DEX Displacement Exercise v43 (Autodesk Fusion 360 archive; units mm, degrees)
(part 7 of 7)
sketch "Sketch40" plane through (0, 0, 0) normal (0, 1, 0) x axis (1, 0, 0)
  line L1 (-93.35, 0) -> (5.1, 0)
  line L2 (-93.35, 50) -> (-93.35, 0)
  line L3 (5.1, 50) -> (-93.35, 50)
  line L4 (5.1, 0) -> (5.1, 50)
  line L5 (-12.25, 50) -> (12.25, 50)
  line L6 (-12.25, 0) -> (-12.25, 50)
  line L7 (12.25, 0) -> (-12.25, 0)
  line L8 (12.25, 50) -> (12.25, 0)
  line L9 (-35.65, 50) -> (-35.65, 0)
  line L10 (-93.35, 25) -> (5.1, 25)
  line L11 (-29, 0) -> (-29, 50)
  line L12 (4.1, 49) -> (-29, 49)
  line L13 (4.1, 1) -> (4.1, 49)
  line L14 (-29, 1) -> (4.1, 1)
  line L15 (3.6, 50) -> (3.6, 0)
  line L16 (-3.6, 50) -> (-3.6, 0)
  line L17 (19.9, 0) -> (12.25, 0)
  line L18 (19.9, 50) -> (19.9, 0)
  line L19 (12.25, 50) -> (19.9, 50)
  circle C1 centre (-88.35, 5) radius 1.575
  circle C2 centre (-17, 5) radius 1.575
  circle C3 centre (-17, 20) radius 1.575
  circle C4 centre (-17, 30) radius 2.7
  circle C5 centre (-17, 45) radius 2.7
  circle C6 centre (-25, 45) radius 2.7
  circle C7 centre (-25, 30) radius 2.7
  circle C8 centre (-25, 20) radius 1.575
  circle C9 centre (-25, 5) radius 1.575
  circle C10 centre (-17, 30) radius 1.7
  circle C11 centre (-17, 45) radius 1.7
  circle C12 centre (-25, 45) radius 1.7
  circle C13 centre (-25, 30) radius 1.7
  circle C14 centre (-17, 45) radius 1.575
  circle C15 centre (-17, 30) radius 1.575
  circle C16 centre (-25, 30) radius 1.575
  circle C17 centre (-25, 45) radius 1.575
  point P1 (0, 0)
  point P7 (-12.25, 50)
  point P8 (-12.25, 0)
  point P11 (-35.65, 0)
  point P12 (-35.65, 50)
  point P13 (5.1, 25)
  point P14 (-93.35, 25)
  point P17 (-17, 30)
  point P18 (-17, 45)
  point P16 (-17, 20)
  point P15 (-17, 5)
  point P19 (-25, 45)
  point P20 (-25, 30)
  point P21 (-25, 20)
  point P22 (-25, 5)
  point P27 (-29, 50)
  point P28 (-29, 0)
  point P29 (-29, 49)
  point P32 (-29, 1)
  point P37 (3.6, 0)
  point P39 (-3.6, 0)
  point P40 (-3.6, 50)
  point P38 (3.6, 50)
  point P6 (12.25, 50)
  point P43 (12.25, 50)
  point P3 (-93.35, 0)
  point P4 (-93.35, 50)
  point P9 (12.25, 0)
  point P10 (-88.35, 5)
  point P25 (-25, 45)
  point P2 (5.1, 0)
  horizontal L1
  vertical L2
  horizontal L3
  vertical L4
  horizontal L5
  vertical L6
  horizontal L7
  vertical L8
  midpoint P1 L7
  coincident L3 P7
  coincident L1 P8
  coincident L1 P11
  coincident L3 P12
  perpendicular L3 L9
  midpoint L4 P13
  midpoint L2 P14
  vertical P17 P18
  vertical P16 P18
  vertical P15 P18
  vertical P19 P20
  vertical P19 P21
  horizontal P18 P19
  horizontal P17 P20
  horizontal P16 P21
  horizontal P15 P22
  vertical P19 P22
  equal C4 C7
  equal C6 C7
  equal C5 C6
  equal C2 C9
  equal C2 C3
  equal C3 C8
  concentric C4 C10
  concentric C5 C11
  concentric C6 C12
  concentric C7 C13
  equal C10 C11
  equal C11 C12
  equal C10 C13
  coincident L3 P27
  coincident L1 P28
  perpendicular L1 L11
  coincident L11 P29
  perpendicular L8 L12
  perpendicular L12 L13
  coincident L11 P32
  perpendicular L11 L14
  concentric C5 C14
  concentric C4 C15
  concentric C7 C16
  concentric C6 C17
  equal C16 C17
  equal C15 C17
  equal C14 C17
  equal C3 C14
  coincident L7 P37
  perpendicular L12 L15
  coincident L1 P39
  perpendicular L12 L16
  coincident L5 P40
  coincident L5 P38
  perpendicular L8 L17
  perpendicular L7 L18
  perpendicular L18 L19
  coincident P6 P43
  dimension "d1502" distance P3 P4 = 50
  dimension "d1503" distance P8 P9 = 24.5
  dimension "d1506" diameter C1 = 3.15
  dimension "d1507" distance L2 P10 = 5
  dimension "d1508" distance L1 P10 = 5
  dimension "d1513" distance L4 P15 = 5
  dimension "d1515" distance P1 P22 = 25
  dimension "d1517" distance L1 P15 = 5
  dimension "d1518" distance P15 P16 = 15
  dimension "d1519" distance P16 P17 = 10
  dimension "d1520" distance P17 P18 = 15
  dimension "d1521" diameter C3 = 3.15
  dimension "d1522" diameter C4 = 5.4 (= "hw_m3insert_d")
  dimension "d1523" distance C4 C10 = 1
  dimension "d1524" distance P25 L11 = 4
  dimension "d1525" distance P22 L14 = 4
  dimension "d1527" distance P18 L12 = 4
  dimension "d1554" distance P1 L2 = 93.35
  dimension "d1555" distance P1 L9 = 35.65
  dimension "d1556" distance P1 L16 = 3.6 (= "t_sheet_MAIN / 2 + 0.25 mm")
  dimension "d1557" distance P1 L15 = 3.6 (= "d1556")
  dimension "d1562" distance P2 L13 = 1
  dimension "d1563" distance P15 P22 = 8
  dimension "d1564" distance L13 L15 = 0.5
  dimension "d1565" distance L9 L11 = 6.65
  dimension "d1568" distance P2 L18 = 14.8
  dimension "d1413" diameter = 7.5
  dimension "d1414" TaperAngle = 0
  dimension "d1415" Side2TaperAngle = 0
  dimension "d1416" ProfileOffset = 0
  dimension "d1417" AlongDistance = 4
  dimension "d1418" TaperAngle = 0
  dimension "d1419" leftDistance = 0.25
  dimension "d1420" ProfileOffset = -10
  dimension "d1421" TaperAngle = 0
  dimension "d1422" ProfileOffset = 4
  dimension "d1423" TaperAngle = 0
  dimension "d1424" ProfileOffset = 10
  dimension "d1425" TaperAngle = 0
  dimension "d1426" leftDistance = 2.175
  dimension "d1427" leftDistance = 1
  dimension "d1428" leftDistance = 0.5
  dimension "d1429" leftDistance = 0.5
  dimension "d1430" diameter = 16 (= "od_bearings")
  dimension "d1431" distance = 1.7
  dimension "d1432" distance = 1.7
  dimension "d1433" distance = 1.5
  dimension "d1434" AlongDistance = 4.5 (= "9.5 mm - t_bearings")
  dimension "d1435" TaperAngle = 0
  dimension "d1436" AlongDistance = 9.5
  dimension "d1437" TaperAngle = 0
  dimension "d1438" ProfileOffset = 9.5
  dimension "d1439" AlongDistance = -0.5
  dimension "d1440" TaperAngle = 0
  dimension "d1441" leftDistance = 1.7
  dimension "d1442" leftDistance = 1
  dimension "d1443" leftDistance = 0.5
  dimension "d1445" leftDistance = 0.5
  dimension "d1446" rightDistance = 1.5
  dimension "d1447" leftDistance = 0.5
  dimension "d1449" distance = 5
  dimension "d1450" distance = 15
  dimension "d1452" distance = 5
  dimension "d1453" distance = 4.9
  dimension "d1454" distance = 4.9
  dimension "d1455" distance = 5
  dimension "d1456" distance = 24.9
  dimension "d531" countU = 13 (= "nh_gantry_length + 1")
  dimension "d532" CountV = 9 (= "nh_gantry_width + 1")
  dimension "d533" uSpaceDistance = 10
  dimension "d534" vSpaceDistance = -10
  dimension "d535" diameter = 3.3 (= "hw_m4_tappedwj")
  dimension "d541" uSpaceDistance = 10
  dimension "d542" vSpaceDistance = 10
  dimension "d560" distance = 6.6 (= "t_sheet_MAIN")
  dimension "d563" distance = 5 (= "t_bearings")
  dimension "d564" distance = 16 (= "od_bearings")
  dimension "d565" angle = 45 (= "d566")
  dimension "d566" angle = 45
  dimension "d567" distance = 10 (= "l_shoulder_thread")
  dimension "d568" distance = 6.6 (= "t_sheet_MAIN")
  dimension "d569" distance = 45 (= "( ( nh_gantry_width * 10 ) * 1 mm + 10 mm ) / 2")
  dimension "d571" distance = 4.5 (= "hw_shoulder_headHeight + 0.5 mm")
  dimension "d572" distance = 4.5 (= "hw_shoulder_headDiameter / 2")
  dimension "d574" distance = 8.8037
  dimension "d576" distance = 0.5
  dimension "d577" distance = 0.5
  dimension "d580" distance = 0.5
  dimension "d581" distance = 3.5 (= "hw_m4insert_d / 2 + 0.5 mm")
  dimension "d582" distance = 3.5 (= "d581")
  dimension "d583" distance = 2.1
  dimension "d584" distance = 0.8383
  dimension "d586" distance = 1.269 (= "0.5 mm + 0.769 mm")
  dimension "d587" distance = 5
  dimension "d588" distance = 10
  dimension "d589" distance = 5
  dimension "d590" AlongDistance = 65 (= "( nh_gantry_length * 10 + 10 ) / 2 * 1 mm")
  dimension "d591" TaperAngle = 0
  dimension "d597" ProfileOffset = 0.25 (= "carriage_offsets")
  dimension "d599" TaperAngle = 0
  dimension "d601" diameter = 16 (= "od_bearings")
  dimension "d602" diameter = 6 (= "hw_m4insert_d")
  dimension "d603" diameter = 4
  dimension "d604" distance = 0.25
  dimension "d606" AlongDistance = -20
  dimension "d607" TaperAngle = 0
  dimension "d608" ProfileOffset = 0.5
  dimension "d609" AlongDistance = 5 (= "t_bearings")
  dimension "d610" TaperAngle = 0
  dimension "d612" distance = 0.25
  dimension "d613" diameter = 4
  dimension "d614" diameter = 6 (= "hw_m4insert_d")
  dimension "d615" diameter = 16 (= "od_bearings")
  dimension "d616" AlongDistance = -20
  dimension "d617" TaperAngle = 0
  dimension "d618" ProfileOffset = 0.5
  dimension "d619" AlongDistance = 5 (= "t_bearings")
  dimension "d620" TaperAngle = 0
  dimension "d621" AlongDistance = 670 (= "l_actual_complete")
  dimension "d622" TaperAngle = 0
  dimension "d623" distance = 0.1
  dimension "d624" distance = 1.6455
  dimension "d625" distance = 3.4128
  dimension "d626" distance = 13.2 (= "0.5 in + 0.5 mm")
  dimension "d628" distance = 5
  dimension "d630" distance = 30
  dimension "d631" diameter = 4.064 (= "hw_n6_thru")
  dimension "d636" diameter = 6.6548 (= "hw_n6_flathead")
  dimension "d637" diameter = 3.1 (= "hw_n6_thread")
  dimension "d638" distance = 4
  dimension "d639" distance = 4 (= "d638")
  dimension "d641" TaperAngle = 0
  dimension "d642" ProfileOffset = 0
  dimension "d643" Side1Offset = 0
  dimension "d644" TaperAngle = 0
  dimension "d645" ProfileOffset = 0
  dimension "d646" Side1Offset = 0
  dimension "d647" TaperAngle = 0
  dimension "d648" distance = 5
  dimension "d649" distance = 0.75
  dimension "d650" ProfileOffset = 0
  dimension "d651" Side1Offset = 0
  dimension "d652" TaperAngle = 0
  dimension "d653" AlongDistance = 21
  dimension "d654" TaperAngle = 0
  dimension "d655" distance = 1
  dimension "d656" ProfileOffset = 0
  dimension "d657" Side1Offset = 0
  dimension "d658" TaperAngle = 0
  dimension "d659" AlongDistance = 12
  dimension "d660" TaperAngle = 0
  dimension "d661" Side1Offset = 0
  dimension "d662" TaperAngle = 0
  dimension "d667" Radius = 4
  dimension "d669" Radius = 4
  dimension "d670" Radius = 1
  dimension "d673" Radius = 0.5
  dimension "d674" Radius = 0.5
  dimension "d675" Radius = 0.5
  dimension "d676" Radius = 0.5
  dimension "d677" Radius = 0.2
  dimension "d680" distance = 40
  dimension "d681" distance = 6
  dimension "d691" distance = 2.54
  dimension "d692" distance = 0.5 (= "d689")
  dimension "d693" distance = 0.5
  dimension "d696" distance = 0.5
  dimension "d697" distance = 5
  dimension "d701" distance = 1.7
  dimension "d702" distance = 1.7 (= "d701")
  dimension "d706" distance = 2.54 (= "d691")
  dimension "d707" distance = 3.5
  dimension "d708" distance = 0.5
  dimension "d709" ProfileOffset = 0
  dimension "d710" Side1Offset = 0
  dimension "d711" TaperAngle = 0
  dimension "d712" ProfileOffset = 0
  dimension "d713" Side1Offset = 5
  dimension "d714" TaperAngle = 0
  dimension "d715" Side1Offset = 0
  dimension "d716" TaperAngle = 0
  dimension "d717" distance = 0.75
  dimension "d718" distance = 1.7
  dimension "d719" diameter = 16 (= "od_bearings")
  dimension "d720" diameter = 6 (= "hw_m4insert_d")
  dimension "d721" diameter = 4
  dimension "d722" distance = 0.25
  dimension "d723" AlongDistance = -19
  dimension "d724" TaperAngle = 0
  dimension "d725" distance = 1
  dimension "d726" ProfileOffset = 0.5
  dimension "d727" AlongDistance = 5 (= "t_bearings")
  dimension "d728" TaperAngle = 0
  dimension "d729" diameter = 4
  dimension "d730" diameter = 6 (= "hw_m4insert_d")
  dimension "d731" diameter = 16 (= "od_bearings")
  dimension "d732" distance = 1
  dimension "d733" distance = 0.25
  dimension "d734" AlongDistance = -26
  dimension "d735" TaperAngle = 0
  dimension "d736" ProfileOffset = 0.5
  dimension "d737" AlongDistance = 5 (= "t_bearings")
  dimension "d738" TaperAngle = 0
  dimension "d739" distance = 6
  dimension "d740" ProfileOffset = 0
  dimension "d741" Side1Offset = 0
  dimension "d742" TaperAngle = 0
  dimension "d743" Radius = 4
  dimension "d745" AlongDistance = 32
  dimension "d746" TaperAngle = 0
  dimension "d747" distance = 0.5
  dimension "d748" distance = 1
  dimension "d749" ProfileOffset = 0
  dimension "d750" AlongDistance = 3
  dimension "d751" TaperAngle = 0
  dimension "d752" ProfileOffset = 0
  dimension "d753" Side1Offset = 0
  dimension "d754" TaperAngle = 0
  dimension "d755" Side1Offset = 0
  dimension "d756" TaperAngle = 0
  dimension "d757" ProfileOffset = 0
  dimension "d758" Side1Offset = 0
  dimension "d759" TaperAngle = 0
  dimension "d760" AlongDistance = 12
  dimension "d761" TaperAngle = 0
  dimension "d762" AlongDistance = -37
  dimension "d763" TaperAngle = 0
  dimension "d764" Side1Offset = 0.5
  dimension "d765" TaperAngle = 0
  dimension "d767" Radius = 3
  dimension "d768" Radius = 2
  dimension "d770" Radius = 3
  dimension "d771" Radius = 3
  dimension "d774" Radius = 1
  dimension "d775" Radius = 0.5
  dimension "d776" Radius = 2
  dimension "d777" diameter = 5.4 (= "hw_m3insert_d")
  dimension "d778" diameter = 3.5 (= "hw_m3_thru")
  dimension "d779" Side1Offset = 0
  dimension "d780" TaperAngle = 0
  dimension "d781" Side1Offset = 0
  dimension "d782" TaperAngle = 0
  dimension "d783" Radius = 2
  dimension "d784" Radius = 2
  dimension "d785" Radius = 2
  dimension "d786" Radius = 3
  dimension "d788" Radius = 0.5
  dimension "d789" distance = 12
  dimension "d790" distance = 2
  dimension "d791" angle = 45
  dimension "d793" Radius = 2
  dimension "d794" Radius = 2
  dimension "d795" Radius = 1
  dimension "d797" Radius = 2
  dimension "d798" Radius = 1
  dimension "d799" Radius = 2
  dimension "d800" Radius = 4.5
  dimension "d801" distance = 0.275 (= "preload_bearings / 2")
  dimension "d806" distance = 3
  dimension "d807" AlongDistance = -60
  dimension "d808" distance = 3.8274 (= "d430 / 2")
  dimension "d809" distance = 0.423 (= "1 mm - 0.577 mm")
  dimension "d810" distance = 0.5
  dimension "d813" Side1Offset = 0
  dimension "d814" TaperAngle = 0
  dimension "d815" distance = 0.1
  dimension "d816" distance = 1.75
  dimension "d818" distance = 35
  dimension "d820" distance = 5
  dimension "d821" distance = 5
  dimension "d822" diameter = 4.064 (= "hw_n6_thru")
  dimension "d823" diameter = 6.6548 (= "hw_n6_flathead")
  dimension "d824" distance = 0.6
  dimension "d825" distance = 0.6 (= "d824")
  dimension "d827" TaperAngle = 0
  dimension "d828" diameter = 3.1 (= "hw_n6_thread")
  dimension "d829" Side1Offset = 0
  dimension "d830" TaperAngle = 0
  dimension "d831" distance = 4
  dimension "d832" distance = 4.477 (= "d833")
  dimension "d833" distance = 4.477 (= "d477")
  dimension "d836" diameter = 6.6548 (= "hw_n6_flathead")
  dimension "d839" Side1Offset = 0
  dimension "d840" TaperAngle = 0
  dimension "d841" distance = 0.9
  dimension "d842" angle = 50
  dimension "d843" angle = 50
  dimension "d844" distance = 8
  dimension "d845" distance = 5
  dimension "d846" diameter = 4.5
  dimension "d847" AlongDistance = -7
  dimension "d848" TaperAngle = 0
  dimension "d849" leftDistance = 0.75
  dimension "d850" ProfileOffset = 0
  dimension "d851" Side1Offset = 0
  dimension "d852" TaperAngle = 0
  dimension "d853" ProfileOffset = 0
  dimension "d854" Side1Offset = 0
  dimension "d855" TaperAngle = 0
  dimension "d856" distance = 12.7
  dimension "d857" leftDistance = 1.5
  dimension "d858" distance = 1.5454
  dimension "d859" Radius = 4
  dimension "d860" Radius = 2
  dimension "d861" Radius = 2
  dimension "d862" Radius = 4
  dimension "d863" Radius = 2
  dimension "d864" Radius = 35
  dimension "d865" Radius = 4
  dimension "d866" Radius = 1
  dimension "d869" Side1Offset = 0
  dimension "d870" TaperAngle = 0
  dimension "d872" distance = 1.5
  dimension "d873" leftDistance = 1.5
  dimension "d874" Radius = 2
  dimension "d885" distance = 27.775
  dimension "d886" distance = 30.275 (= "30 mm + preload_bearings / 2")
  dimension "d889" diameter = 3.3 (= "hw_m4_tappedwj")
  dimension "d890" distance = 5
  dimension "d891" distance = 10.275 (= "10 mm + preload_bearings / 2")
  dimension "d893" TaperAngle = 0
  dimension "d894" distance = 17.5
  dimension "d895" distance = 27.5
  dimension "d896" distance = 0.2
  dimension "d897" distance = 0.2 (= "d896")
  dimension "d900" distance = 6
  dimension "d902" distance = 3.7 (= "2 mm + 1.2 mm + 0.5 mm")
  dimension "d903" distance = 1
  dimension "d904" distance = 8
  dimension "d905" distance = 2.54
  dimension "d906" distance = 2.54
  dimension "d907" distance = 2.54
  dimension "d908" Side1Offset = 0
  dimension "d909" TaperAngle = 0
  dimension "d910" ProfileOffset = 0
  dimension "d911" Side1Offset = 0
  dimension "d912" TaperAngle = 0
  dimension "d913" leftDistance = 1.5
  dimension "d915" distance = 5.65
  dimension "d916" distance = 14.65
  dimension "d917" distance = 14.65
  dimension "d918" Side1Offset = 0
  dimension "d919" TaperAngle = 0
  dimension "d920" ChordLen = 4
  dimension "d921" ChordLen = 1
  dimension "d923" distance = 2.54
  dimension "d924" Radius = 2
extrude "Extrude159" new body sketch "Sketch40" profile of L1 L2 L3 L4 L5 L6 L7 L8 C1 L10 C2 C3 C4 C5 C6 C7 C8 C9 C10 C11 C12 C13 L11 L12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 blind 6.7 (= "t_sheet_MAIN") from offset 30.1
extrude "Extrude160" sketch "Sketch40" profile of L6 L10 C2 C3 C4 C5 C6 C7 C8 C9 C10 C11 C12 C13 L11 L12 L14 C14 C15 C16 C17 L16 blind -0.9 from offset -0.05
extrude "Extrude161" sketch "Sketch40" profile of L6 L10 C2 C3 C4 C5 C6 C7 C8 C9 C10 C11 C12 C13 L11 L12 L14 C14 C15 C16 C17 L16 to an object offset 3.35 (= "t_sheet_MAIN / 2")
extrude "Extrude162" cut sketch "Sketch40" profile of C2 C3 C8 C9 C10 C11 C12 C13 C14 C15 C16 C17 to an object
extrude "Extrude163" sketch "Sketch40" profile of C4 C5 C6 C7 C10 C11 C12 C13 blind 7
extrude "Extrude164" sketch "Sketch40" profile of C4 C5 C6 C7 C10 C11 C12 C13 blind -7
chamfer "Chamfer37" distance 1
chamfer "Chamfer38" distance 0.5
fillet "Fillet112" radius 1
extrude "Extrude165" cut sketch "Sketch40" profile of C1 no distance stored
rectangular_pattern "R-Pattern5" uSpaceDistance 10 vSpaceDistance 10
extrude "Extrude166" sketch "Sketch40" profile of L6 L8 L10 L12 L14 L15 L16 blind 11
fillet "Fillet113" radius 2
copy_paste_bodies "CopyPasteBodies2"
move "Move2"
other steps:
base_feature "Base Feature"
step "OffsetFaces9" distance 3
step "Combine8"
step "OffsetFaces7" distance -1
step "Combine7"
step "OffsetFaces8" distance 3
step "OffsetFaces10" distance -0.5
step "Mirror"
step "Combine9"
step "Combine10"
step "Combine11"

design "rct-lb-perp-pincer-t"
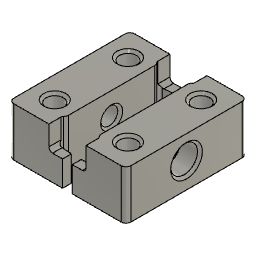
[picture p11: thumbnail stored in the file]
parameter "m3insert_d" = 5.5
parameter "m3thru_d" = 3.5
parameter "t_sheet_MAIN" = 6.7
sketch "Sketch1" plane through (0, 0, 0) normal (0, 0, 1) x axis (1, 0, 0)
  line L1 (0, -12.4) -> (0, 12.4)
  line L2 (3.35, 12.4) -> (-3.35, 12.4)
  line L3 (3.35, -12.4) -> (3.35, 12.4)
  line L4 (-3.35, -12.4) -> (3.35, -12.4)
  line L5 (-3.35, 12.4) -> (-3.35, -12.4)
  line L6 (-1, 10.6056) -> (-1, 12.4)
  line L7 (-3.35, 10.4) -> (-1, 10.6056)
  line L8 (-3.35, 0) -> (-3.35, 9.4038)
  line L9 (-12, 12.4) -> (-1, 12.4)
  line L10 (-12, 0) -> (-12, 12.4)
  line L11 (-3.35, 0) -> (-12, 0)
  line L12 (-3.8064, 12.4) -> (-3.8064, 9.9019)
  circle C1 centre (-7.5, 7.5) radius 2.75
  circle C2 centre (-7.5, 7.5) radius 1.75
  arc A1 centre (-3.3064, 9.9019) radius 0.5 clockwise from (-3.35, 9.4038) to (-3.35, 10.4)
  point P1 (0, 0)
  point P2 (0, 12.4)
  point P3 (0, -12.4)
  point P10 (-1, 12.4)
  point P12 (-3.35, 10.4)
  point P13 (-3.35, 9.4038)
  point P14 (-3.35, 0)
  point P18 (-3.35, 0)
  point P19 (-3.8064, 9.9019)
  point P20 (-3.8064, 12.4)
  point P6 (3.35, -12.4)
  point P7 (-3.35, -12.4)
  point P8 (-7.5, 7.5)
  point P4 (-3.35, 12.4)
  point P16 (-12, 12.4)
  vertical L1
  midpoint P1 L1
  horizontal L2
  vertical L3
  horizontal L4
  vertical L5
  midpoint P2 L2
  midpoint P3 L4
  concentric C1 C2
  coincident L2 P10
  perpendicular L2 L6
  coincident L5 P12
  coincident L5 P13
  midpoint L5 P14
  parallel L5 L8
  tangent L7 A1
  perpendicular L6 L9
  perpendicular L9 L10
  perpendicular L10 L11
  coincident P14 P18
  midpoint A1 P19
  coincident L9 P20
  tangent A1 L12
  perpendicular L9 L12
  dimension "d91" distance P2 P3 = 24.8
  dimension "d92" distance P6 P7 = 6.7 (= "t_sheet_MAIN")
  dimension "d95" distance P1 P8 = 7.5
  dimension "d98" diameter C2 = 3.5 (= "m3thru_d")
  dimension "d99" radius A1 = 0.5
  dimension "d101" angle L6 L7 = 85
  dimension "d102" distance P4 P12 = 2
  dimension "d103" distance P2 L6 = 1
  dimension "d104" diameter C1 = 5.5 (= "m3insert_d")
  dimension "d127" distance P1 P8 = 7.5
  dimension "d128" distance L1 P16 = 12
extrude "Extrude14" new body sketch "Sketch1" profile of C1 C2 L6 L7 L8 A1 L9 L10 L11 L12 against normal blind 10 bodies "rct-lb-perp-pincer-left"
extrude "Extrude15" cut sketch "Sketch1" profile of L6 L7 A1 L9 L12 against normal blind 4.8
fillet "Fillet5" radius 0.75
sketch "Sketch7" plane through (-3.35, 0, 0) normal (1, 0, 0) x axis (0, 1, 0)
  line L1 (0, 0) -> (9.4038, 0)
  line L2 (0, -10) -> (0, 0)
  line L3 (9.4038, -10) -> (0, -10)
  line L4 (9.4038, 0) -> (9.4038, -10)
  circle C1 centre (0, -4.8) radius 2.75
  circle C2 centre (0, -4.8) radius 1.75
  circle C3 centre (0, -4.8) radius 3.625
  point P6 (0, -4.8)
  point P1 (0, 0)
  point P7 (0, -4.8)
  coincident L2 P6
  concentric C1 C2
  concentric C1 C3
  dimension "d111" diameter C1 = 5.5 (= "m3insert_d")
  dimension "d112" diameter C2 = 3.5 (= "m3thru_d")
  dimension "d113" distance P1 P7 = 4.8
  dimension "d132" diameter C3 = 7.25
extrude "Extrude16" cut sketch "Sketch7" profile of L2 C2 no distance stored
extrude "Extrude17" cut sketch "Sketch1" profile of C2 no distance stored
work_plane "WorkPlane1" AlongDistance 3.35 (= "t_sheet_MAIN / 2")
fillet "Fillet6" radius 1
extrude "Extrude18" sketch "Sketch1" profile of C1 C2 blind 4
chamfer "Chamfer4" distance 0.7
chamfer "Chamfer5" distance 0.5
mirror "Mirror2"
combine "Combine2"
mirror "Mirror3" bodies "rct-lb-perp-pincer-right"
extrude "Extrude21" sketch "Sketch7" profile of L2 C1 C2 blind -4
extrude "Extrude22" sketch "Sketch7" profile of L2 C1 C2 C3 blind 4
chamfer "Chamfer11" distance 0.5
chamfer "Chamfer12" distance 0.7
chamfer "Chamfer13" distance 0.5
fillet "Fillet8" radius 1
named bodies: "rct-lb-perp-pincer-left", "rct-lb-perp-pincer-right"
